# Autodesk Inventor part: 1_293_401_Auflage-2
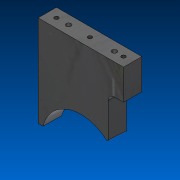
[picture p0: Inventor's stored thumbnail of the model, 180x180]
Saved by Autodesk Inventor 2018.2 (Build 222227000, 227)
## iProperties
Created: 2018-02
Part Number: 1_293_401_Auflage-2
Material: POM (schwarz)
Document SubType Name: Modeling
Designer: Winfried.Bach
Density: 1.14 g/cm^3
Appearance: Glatt - mittelgrau
Author: Winfried.Bach
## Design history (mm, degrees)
sketch "Skizze10"
  geometry: L1 (70, 15)-(-70, 15); L2 (-70, 15)-(-70, -15); L3 (-70, -15)-(70, -15); L4 (70, -15)-(70, 15); L5 (70, 15)-(-70, -15); L6 (-70, 15)-(70, -15); 1 further point
  constraints: 12 end point, 2 midpoint, 2 parallel, 1 horizontal, 1 perpendicular
  dimensions: "d56" = 30 distance of L1.end L2.end; "d57" = 140 distance of L2.end L3.end
extrude "Extrusion6" new body sketch "Skizze10" distance "d58" = 150; taper "d59" = 0 deg
sketch "Skizze11"
  geometry: 5 further points
  constraints: 4 horizontal alignment
  dimensions: "d60" = 55 distance of point (0, 0) point (55, 0); "d61" = 55 distance of point (-55, 0) point (0, 0); "d62" = 15 distance of point (40, 0) point (55, 0); "d63" = 20 distance of point (-55, 0) point (-35, 0)
hole "Bohrung5" sketch "Skizze11" diameter "d64" = 6.647; stored, may be unused: countersink angle "d68" = 90 deg, drill point angle "d70" = 118 deg; dims "d65" = 20, "d66" = 4, "d67" = 2, "d69" = 25
hole "Bohrung6" sketch "Skizze11" diameter "d71" = 8; stored, may be unused: countersink angle "d75" = 90 deg, drill point angle "d77" = 118 deg; dims "d72" = 20, "d73" = 4, "d74" = 2, "d76" = 20
sketch "Skizze12"
  geometry: L1 (140, 0)-(115, 0); L2 (115, 0)-(115, -100); L3 (115, -100)-(140, -100); L4 (140, -100)-(140, 0); 2 further points
  constraints: 8 end point, 2 parallel, 1 coincident, 1 horizontal, 1 perpendicular
  dimensions: "d78" = 100 distance of L1.end L2.end; "d79" = 25 distance of L2.end L3.end
extrude "Extrusion7" cut sketch "Skizze12" extent not by distance; stored distance "d80" = 10; taper "d81" = 0 deg
fillet "Rundung1" dims "d82" = 10
feature "Basis4"
feature "Kombinieren3"
  node "Volumenkörper6"
feature "Fläche löschen3"
feature "Fläche löschen4"
fillet "Rundung2" dims "d83" = 2
node "Volumenkörper4"
node "Volumenkörpern"
node "Oberflächenkörpern"
